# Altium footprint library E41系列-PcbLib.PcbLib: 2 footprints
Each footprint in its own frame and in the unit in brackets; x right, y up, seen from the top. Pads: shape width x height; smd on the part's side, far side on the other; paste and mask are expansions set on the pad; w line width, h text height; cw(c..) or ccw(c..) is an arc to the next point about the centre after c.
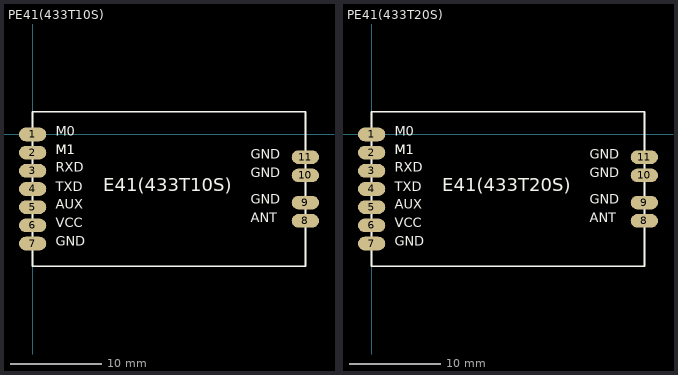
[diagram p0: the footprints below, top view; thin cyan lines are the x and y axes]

## PE41(433T10S) [mm] "30mm*17mm*3.5mm-S"
pads (11):
  oval 3x1.5 smd: 1(0,0) 2(0,-2) 3(0,-4) 4(0,-6) 5(0,-8) 6(0,-10) 7(0,-12) 8(30,-9.5) 9(30,-7.5) 10(30,-4.5) 11(30,-2.5)
Top Overlay:
  lines w0.2: 0,-14.5 30,-14.5 30,2.5 0,2.5 0,-14.5
  text "ANT" at 24.017,-10.064 h1.8
  text "GND" at 24.017,-8.032 h1.8
  text "GND" at 24.017,-5.111 h1.8
  text "GND" at 24.017,-3.079 h1.8
  text "GND" at 2.554,-12.604 h1.8
  text "VCC" at 2.554,-10.572 h1.8
  text "TXD" at 2.554,-6.635 h1.8
  text "RXD" at 2.554,-4.476 h1.8
  text "M1" at 2.554,-2.571 h1.8
  text "M1" at 2.554,-2.571 h1.8
  text "M0" at 2.554,-0.539 h1.8
  text "AUX" at 2.554,-8.54 h1.8
  text "E41(433T10S)" at 7.761,-6.762 h2.5

## PE41(433T20S) [mm] "30mm*17mm*3.5mm-S"
pads (11):
  oval 3x1.5 smd: 1(0,0) 2(0,-2) 3(0,-4) 4(0,-6) 5(0,-8) 6(0,-10) 7(0,-12) 8(30,-9.5) 9(30,-7.5) 10(30,-4.5) 11(30,-2.5)
Top Overlay:
  lines w0.2: 0,-14.5 0,2.5 30,2.5 30,-14.5 0,-14.5
  text "E41(433T20S)" at 7.761,-6.762 h2.5
  text "AUX" at 2.554,-8.54 h1.8
  text "M0" at 2.554,-0.539 h1.8
  text "M1" at 2.554,-2.571 h1.8
  text "M1" at 2.554,-2.571 h1.8
  text "RXD" at 2.554,-4.476 h1.8
  text "TXD" at 2.554,-6.635 h1.8
  text "VCC" at 2.554,-10.572 h1.8
  text "GND" at 2.554,-12.604 h1.8
  text "GND" at 24.017,-3.079 h1.8
  text "GND" at 24.017,-5.111 h1.8
  text "GND" at 24.017,-8.032 h1.8
  text "ANT" at 24.017,-10.064 h1.8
